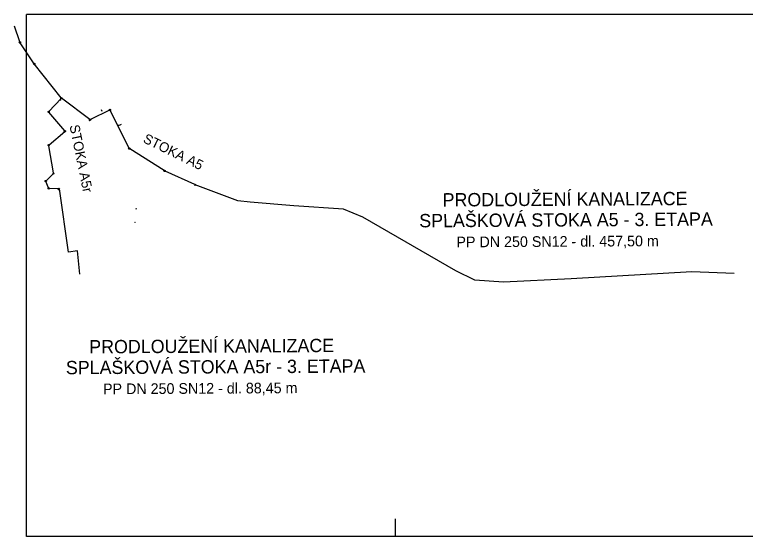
# Model space of a CAD drawing. Extents: x -969087 to -122837, y -1605141 to -636627.
# Drawn here: x -545737.3 to -545529.4, y -1121871.8 to -1121723.3 of the extents above; entities that cross this region are included whole.
import ezdxf

# ---------------------------------------------------------------- set-up
doc = ezdxf.new("R2010")
doc.units = 0
for name, color, linetype in [('1_KANAL SPL NOVÁ_STOKY 2 ET', 7, 'Continuous'), ('1_VODA_ZN', 7, 'Continuous'), ('26_SRAFY', 7, 'Continuous'), ('2_KANAL STOKA_POPIS', 7, 'Continuous'), ('4_ŠACHTY_OBJEKTY', 7, 'Continuous'), ('Implicitní', 7, 'Continuous'), ('ODBOČKY ZE STOKY', 7, 'Continuous'), ('PŘÍPOJKY SPLAŠKOVÉ', 7, 'Continuous'), ('ZOV POPIS', 7, 'Continuous')]:
    doc.layers.add(name, color=color, linetype=linetype)

# ---------------------------------------------------------------- blocks, each defined once
blk = doc.blocks.new('POINT_DISPLAY')
at = {"layer": 'Implicitní'}
for p, q in [((-2.1, -2.1), (2.1, 2.1)), ((-2.1, 2.1), (2.1, -2.1))]:
    blk.add_line(p, q, dxfattribs=at)

msp = doc.modelspace()

# ---------------------------------------------------------------- linework, layer by layer
at = {"layer": '1_KANAL SPL NOVÁ_STOKY 2 ET'}
for p, q in [((-545735.89, -1121731.05), (-545737.34, -1121726.54)), ((-545731.75, -1121737.31), (-545735.76, -1121731.32)), ((-545724.12, -1121746.97), (-545731.75, -1121737.31)), ((-545727.57, -1121750.84), (-545724.13, -1121747.2)), ((-545715.99, -1121753.11), (-545724.02, -1121747.09)), ((-545710.36, -1121750.46), (-545715.73, -1121753.14)), ((-545704.8, -1121761.27), (-545710.16, -1121750.53)), ((-545723.08, -1121756.33), (-545727.58, -1121751.07)), ((-545727.54, -1121760.34), (-545723.1, -1121756.55)), ((-545726.31, -1121768.35), (-545727.63, -1121760.6)), ((-545694.79, -1121767.68), (-545704.6, -1121761.49)), ((-545724.72, -1121773.27), (-545724.76, -1121773.06))]:
    msp.add_line(p, q, dxfattribs=at)
for points in [[(-545728.37, -1121770.55), (-545726.39, -1121768.61)], [(-545686.11, -1121771.65), (-545694.52, -1121767.83)], [(-545727.69, -1121772.61), (-545728.42, -1121770.8)], [(-545724.94, -1121772.9), (-545727.48, -1121772.76)]]:
    msp.add_lwpolyline(points, dxfattribs=at)
at = {"layer": '26_SRAFY'}
msp.add_line((-545712.39, -1121750.83), (-545712.59, -1121750.37), dxfattribs=at)
at = {"layer": '4_ŠACHTY_OBJEKTY'}
for centre, radius in [((-545735.84, -1121731.19), 0.191), ((-545735.84, -1121731.19), 0.154), ((-545735.81, -1121731.23), 0.0923), ((-545731.75, -1121737.31), 0.191), ((-545731.75, -1121737.31), 0.154), ((-545731.72, -1121737.35), 0.0923), ((-545724.02, -1121747.09), 0.191), ((-545724.02, -1121747.09), 0.154), ((-545723.99, -1121747.13), 0.0923), ((-545710.22, -1121750.39), 0.191), ((-545710.22, -1121750.39), 0.154), ((-545710.19, -1121750.43), 0.0923), ((-545727.68, -1121750.95), 0.191), ((-545727.68, -1121750.95), 0.154), ((-545727.64, -1121750.99), 0.0923), ((-545715.87, -1121753.2), 0.191), ((-545715.87, -1121753.2), 0.154), ((-545715.84, -1121753.24), 0.0923), ((-545722.98, -1121756.45), 0.191), ((-545722.98, -1121756.45), 0.154), ((-545722.95, -1121756.49), 0.0923), ((-545727.66, -1121760.44), 0.191), ((-545727.66, -1121760.44), 0.154), ((-545727.63, -1121760.49), 0.0923), ((-545704.73, -1121761.4), 0.191), ((-545704.73, -1121761.4), 0.154), ((-545704.7, -1121761.45), 0.0923), ((-545726.28, -1121768.5), 0.191), ((-545726.28, -1121768.5), 0.154), ((-545726.33, -1121768.49), 0.0923), ((-545694.66, -1121767.76), 0.191), ((-545694.66, -1121767.76), 0.154), ((-545694.63, -1121767.8), 0.0923), ((-545728.48, -1121770.65), 0.191), ((-545728.48, -1121770.65), 0.154), ((-545728.45, -1121770.69), 0.0923), ((-545685.97, -1121771.72), 0.191), ((-545727.63, -1121772.75), 0.191), ((-545727.63, -1121772.75), 0.154), ((-545727.6, -1121772.79), 0.0923), ((-545724.79, -1121772.91), 0.191), ((-545724.79, -1121772.91), 0.154), ((-545724.76, -1121772.95), 0.0923), ((-545685.97, -1121771.72), 0.154), ((-545685.94, -1121771.76), 0.0923)]:
    msp.add_circle(centre, radius, dxfattribs=at)
at = {"layer": 'Implicitní'}
for p, q in [((-545419, -1121723.28), (-545734, -1121723.28)), ((-545734, -1121871.78), (-545734, -1121723.28)), ((-545629, -1121871.78), (-545629, -1121866.83)), ((-545419, -1121871.78), (-545734, -1121871.78))]:
    msp.add_line(p, q, dxfattribs=at)
for points in [[(-545722, -1121790.85), (-545724.6, -1121772.87)], [(-545670.31, -1121776.68), (-545673.88, -1121776.26), (-545685.97, -1121771.72)], [(-545532.61, -1121796.92), (-545544.69, -1121796.49), (-545578.97, -1121798.46), (-545598.21, -1121799.45), (-545606.36, -1121798.88), (-545611.84, -1121796.21), (-545638.25, -1121780.89), (-545643.73, -1121778.65), (-545657.91, -1121777.66), (-545670.31, -1121776.68)], [(-545718.75, -1121797.12), (-545719.41, -1121790.54), (-545722, -1121790.85)]]:
    msp.add_lwpolyline(points, dxfattribs=at)
at = {"layer": 'ODBOČKY ZE STOKY'}
msp.add_line((-545707.95, -1121754.95), (-545706.98, -1121754.47), dxfattribs=at)
at = {"layer": 'PŘÍPOJKY SPLAŠKOVÉ'}
msp.add_line((-545707.63, -1121754.78), (-545707.92, -1121754.9), dxfattribs=at)
at = {"layer": 'ZOV POPIS'}
msp.add_lwpolyline([(-545726.84, -1121769.14), (-545726.84, -1121769.14)], dxfattribs=at)

# ---------------------------------------------------------------- block references
at = {"layer": '1_VODA_ZN', "xscale": 0.030781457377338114, "yscale": 0.030781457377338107, "rotation": 1.4435747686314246}
for p in [(-545724.38, -1121747.62), (-545724.31, -1121747.54), (-545710.1, -1121750.4), (-545727.55, -1121750.96), (-545716.05, -1121753.37), (-545715.75, -1121753.22), (-545723.28, -1121756.59), (-545702.75, -1121778.51), (-545703.11, -1121782.4)]:
    msp.add_blockref('POINT_DISPLAY', p, dxfattribs=at)

# ---------------------------------------------------------------- texts
at = {"layer": '2_KANAL STOKA_POPIS'}
for s, height, rotation, p in [('STOKA A5r', 2.807, 281.5561, (-545721.74, -1121754.91)), ('STOKA A5', 2.807, 333.8161, (-545701.02, -1121759.52)), ('PRODLOUŽENÍ KANALIZACE', 3.7969, 0.3262, (-545615.57, -1121777.9)), ('SPLAŠKOVÁ STOKA A5 - 3. ETAPA', 3.7969, 0.3262, (-545622.21, -1121783.83)), ('PP DN 250 SN12 - dl. 457,50 m ', 3.0376, 0.3262, (-545611.63, -1121789.52)), ('PRODLOUŽENÍ KANALIZACE', 3.7969, 0.3262, (-545716.11, -1121819.72)), ('SPLAŠKOVÁ STOKA A5r - 3. ETAPA', 3.7969, 0.3262, (-545722.76, -1121825.65)), ('PP DN 250 SN12 - dl. 88,45 m ', 3.0376, 0.3262, (-545712.18, -1121831.33))]:
    msp.add_text(s, height=height, rotation=rotation, dxfattribs=at).set_placement(p)

doc.saveas('drawing.dxf')
